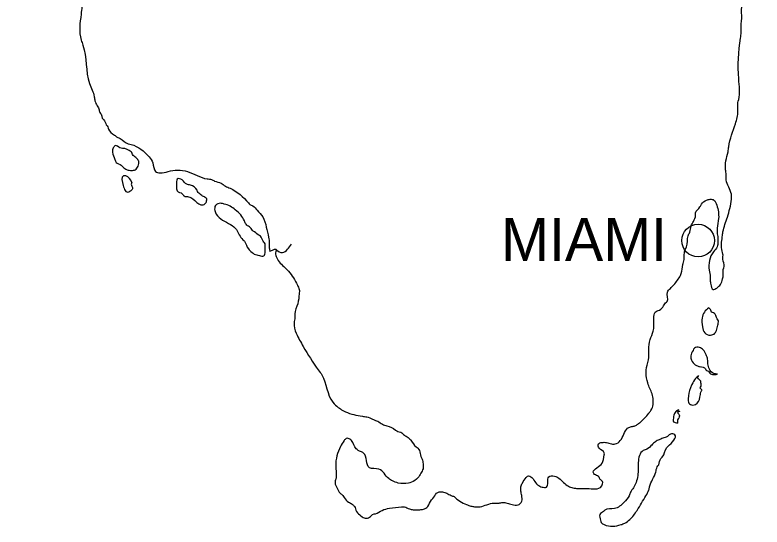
# Model space of a CAD drawing. Extents: x 452225 to 584229, y 1232161 to 1334160.
# Drawn here: x 559573 to 565095, y 1306169 to 1309955 of the extents above; entities that cross this region are included whole.
import ezdxf

# ---------------------------------------------------------------- set-up
doc = ezdxf.new("R2010")
doc.units = 0
doc.layers.add('V-ANNO-SYMB', color=7, linetype='Continuous')

msp = doc.modelspace()

# ---------------------------------------------------------------- linework, layer by layer
at = {"layer": 'V-ANNO-SYMB'}
msp.add_circle((564622, 1308287.4), 120.7, dxfattribs=at)
for points in [[(564684.1, 1308587.1), (564711.1, 1308592.5), (564738.1, 1308587.1), (564759.7, 1308549.3), (564773.2, 1308449.4), (564762.4, 1308379.2), (564762.4, 1308346.8), (564767.8, 1308309), (564767.8, 1308276.6), (564762.4, 1308241.5), (564735.4, 1308203.7), (564703, 1308068.7), (564711.1, 1308017.4), (564711.1, 1307995.8), (564716.5, 1307963.4), (564732.7, 1307925.6), (564759.7, 1307936.4), (564786.7, 1307963.4), (564802.9, 1308003.9), (564808.3, 1308036.3), (564808.3, 1308074.1), (564813.7, 1308095.7), (564805.6, 1308149.7), (564805.6, 1308187.5), (564800.2, 1308209.1), (564800.2, 1308314.4), (564805.6, 1308352.2), (564838, 1308460.2), (564867.7, 1308592.5), (564867.7, 1308630.3), (564829.9, 1308735.6), (564829.9, 1308773.4), (564824.5, 1308811.2), (564827.2, 1308876), (564843.4, 1308943.5), (564848.8, 1308981.3), (564897.4, 1309151.4), (564916.3, 1309243.2), (564916.3, 1309308), (564921.7, 1309329.6), (564921.7, 1309483.5), (564935.2, 1309783.2), (564940.6, 1309826.4), (564940.6, 1309893.9), (564946, 1309937.1), (564943.3, 1310001.9), (564948.7, 1310028.9), (564948.7, 1310072.1), (564954.1, 1310101.8), (564954.1, 1310139.6), (564959.5, 1310166.6), (564959.5, 1310204.4), (564970.3, 1310269.2), (564967.6, 1310307), (564973, 1310347.5), (564973, 1310406.9), (564989.2, 1310487.9), (564989.2, 1310514.9), (565000, 1310560.8), (565000, 1310614.8), (565005.4, 1310652.6), (565002.7, 1310766), (564991.9, 1310838.9), (564991.9, 1310871.3), (564973, 1311000.9), (564973, 1311063), (564967.6, 1311122.4), (564967.6, 1311252), (564973, 1311292.5), (564970.3, 1311395.1), (564975.7, 1311416.7), (564975.7, 1311486.9), (564981.1, 1311527.4), (565002.7, 1311559.8), (565040.5, 1311484.2), (565045.9, 1311449.1), (565056.7, 1311411.3), (565059.4, 1311373.5), (565070.2, 1311308.7), (565070.2, 1311270.9), (565075.6, 1311238.5), (565078.3, 1310998.2), (565072.9, 1310957.7), (565072.9, 1310882.1), (565067.5, 1310849.7), (565067.5, 1310817.3), (565062.1, 1310774.1), (565062.1, 1310752.5), (565078.3, 1310757.9), (565089.1, 1310784.9), (565094.5, 1310828.1)], [(560153.5, 1311370.8), (560180.5, 1311392.4), (560148.1, 1311349.2), (560137.3, 1311338.4), (560029.3, 1311270.9), (559996.9, 1311254.7), (559986.1, 1311233.1), (559964.5, 1311211.5), (559953.7, 1311195.3), (559937.5, 1311184.5), (559932.1, 1311165.6), (559861.9, 1311084.6), (559834.9, 1311063), (559813.3, 1311030.6), (559807.9, 1310995.5), (559797.1, 1310979.3), (559794.4, 1310952.3), (559778.2, 1310914.5), (559756.6, 1310892.9), (559718.8, 1310871.3), (559697.2, 1310855.1), (559659.4, 1310841.6), (559627, 1310836.2), (559594.6, 1310820), (559578.4, 1310776.8), (559573, 1310744.4), (559578.4, 1310712), (559632.4, 1310658), (559654, 1310647.2), (559740.4, 1310620.2), (559807.9, 1310609.4), (559942.9, 1310544.6), (559975.3, 1310517.6), (560013.1, 1310447.4), (560018.5, 1310425.8), (560032, 1310398.8), (560048.2, 1310309.7), (560048.2, 1310277.3), (560053.6, 1310250.3), (560053.6, 1310212.5), (560059, 1310180.1), (560059, 1310126.1), (560067.1, 1310069.4), (560067.1, 1310015.4), (560061.7, 1309961.4), (560061.7, 1309769.7), (560075.2, 1309731.9), (560123.8, 1309448.4), (560158.9, 1309351.2), (560164.3, 1309321.5), (560180.5, 1309283.7), (560191.3, 1309267.5), (560196.7, 1309240.5), (560212.9, 1309213.5), (560218.3, 1309191.9), (560229.1, 1309181.1), (560248, 1309143.3), (560258.8, 1309127.1), (560264.2, 1309110.9), (560307.4, 1309067.7), (560329, 1309051.5), (560350.6, 1309040.7), (560410, 1309002.9), (560431.6, 1308997.5), (560563.9, 1308905.7), (560590.9, 1308862.5), (560612.5, 1308797.7), (560644.9, 1308786.9), (560704.3, 1308797.7), (560847.4, 1308797.7), (560993.2, 1308743.7), (561025.6, 1308738.3), (561047.2, 1308727.5), (561095.8, 1308711.3), (561128.2, 1308689.7), (561163.3, 1308673.5), (561298.3, 1308565.5), (561309.1, 1308554.7), (561330.7, 1308543.9), (561363.1, 1308511.5), (561403.6, 1308462.9), (561430.6, 1308387.3), (561446.8, 1308311.7), (561452.2, 1308268.5), (561452.2, 1308233.4), (561457.6, 1308206.4)], [(560385.7, 1308967.8), (560347.9, 1308973.2), (560315.5, 1308989.4), (560299.3, 1308973.2), (560293.9, 1308940.8), (560310.1, 1308886.8), (560320.9, 1308865.2), (560358.7, 1308843.6), (560369.5, 1308832.8), (560401.9, 1308811.2), (560434.3, 1308805.8), (560461.3, 1308811.2), (560482.9, 1308838.2), (560488.3, 1308876)], [(560488.3, 1308873.3), (560480.2, 1308886.8), (560466.7, 1308900.3), (560453.2, 1308911.1), (560442.4, 1308924.6), (560437, 1308938.1), (560407.3, 1308957), (560385.7, 1308967.8)], [(560437, 1308716.7), (560391.1, 1308765.3), (560374.9, 1308765.3), (560372.2, 1308695.1), (560388.4, 1308657.3), (560399.2, 1308646.5), (560431.6, 1308657.3)], [(560437, 1308716.7), (560431.6, 1308703.2), (560437, 1308689.7), (560442.4, 1308670.8), (560431.6, 1308657.3)], [(560920.3, 1308660), (560869, 1308697.8), (560842, 1308703.2), (560809.6, 1308735.6), (560771.8, 1308741), (560766.4, 1308724.8), (560766.4, 1308687), (560771.8, 1308654.6), (560809.6, 1308633), (560823.1, 1308616.8), (560855.5, 1308611.4), (560887.9, 1308595.2), (560947.3, 1308552), (560963.5, 1308552), (560985.1, 1308568.2), (560990.5, 1308595.2)], [(560990.5, 1308595.2), (560979.7, 1308606), (560966.2, 1308614.1), (560952.7, 1308619.5), (560939.2, 1308633), (560925.7, 1308643.8), (560920.3, 1308660)], [(562818.4, 1306394.7), (562861.6, 1306359.6), (562910.2, 1306335.3), (562942.6, 1306324.5), (562969.6, 1306319.1), (563010.1, 1306319.1), (563112.7, 1306346.1), (563150.5, 1306346.1), (563177.5, 1306351.5), (563209.9, 1306346.1), (563247.7, 1306335.3), (563290.9, 1306332.6), (563317.9, 1306359.6), (563317.9, 1306402.8), (563312.5, 1306435.2), (563312.5, 1306467.6), (563323.3, 1306494.6), (563350.3, 1306535.1), (563361.1, 1306545.9), (563393.5, 1306535.1), (563420.5, 1306497.3), (563452.9, 1306470.3), (563469.1, 1306464.9), (563501.5, 1306464.9), (563517.7, 1306540.5), (563560.9, 1306545.9), (563593.3, 1306529.7), (563663.5, 1306470.3), (563695.9, 1306459.5), (563733.7, 1306454.1), (563801.2, 1306454.1), (563909.2, 1306473), (563914.6, 1306505.4), (563898.4, 1306521.6), (563890.3, 1306537.8), (563863.3, 1306554), (563847.1, 1306575.6), (563874.1, 1306608), (563911.9, 1306640.4), (563928.1, 1306702.5), (563928.1, 1306718.7), (563890.3, 1306751.1), (563884.9, 1306783.5), (563911.9, 1306794.3), (563944.3, 1306794.3), (563982.1, 1306783.5), (564009.1, 1306783.5), (564046.9, 1306807.8), (564100.9, 1306899.6), (564122.5, 1306910.4), (564149.5, 1306915.8), (564171.1, 1306926.6), (564192.7, 1306942.8), (564257.5, 1307010.3), (564273.7, 1307031.9), (564289.9, 1307075.1), (564289.9, 1307107.5), (564287.2, 1307131.8), (564281.8, 1307153.4), (564249.4, 1307234.4), (564249.4, 1307385.6), (564254.8, 1307404.5), (564257.5, 1307480.1), (564268.3, 1307555.7), (564289.9, 1307617.8), (564295.3, 1307655.6), (564295.3, 1307725.8), (564311.5, 1307763.6), (564327.7, 1307769), (564360.1, 1307796), (564381.7, 1307825.7), (564392.5, 1307836.5), (564395.2, 1307906.7), (564416.8, 1307933.7), (564427.6, 1307944.5), (564481.6, 1308012), (564497.8, 1308044.4), (564508.6, 1308109.2), (564519.4, 1308147), (564519.4, 1308174), (564524.8, 1308214.5), (564535.6, 1308241.5), (564549.1, 1308322.5), (564559.9, 1308349.5), (564570.7, 1308395.4), (564586.9, 1308427.8), (564603.1, 1308476.4), (564603.1, 1308492.6), (564635.5, 1308535.8), (564646.3, 1308557.4), (564684.1, 1308587.1)], [(561268.6, 1308433.2), (561241.6, 1308476.4), (561201.1, 1308514.2), (561163.3, 1308541.2), (561120.1, 1308557.4), (561093.1, 1308562.8), (561055.3, 1308546.6), (561049.9, 1308508.8), (561060.7, 1308481.8), (561106.6, 1308438.6), (561166, 1308406.2), (561209.2, 1308368.4), (561230.8, 1308330.6), (561257.8, 1308292.8), (561268.6, 1308282), (561298.3, 1308225.3), (561309.1, 1308214.5), (561341.5, 1308187.5), (561379.3, 1308176.7), (561411.7, 1308174), (561422.5, 1308206.4), (561422.5, 1308233.4), (561417.1, 1308271.2), (561406.3, 1308282), (561398.2, 1308303.6), (561371.2, 1308330.6), (561333.4, 1308357.6)], [(561333.4, 1308357.6), (561322.6, 1308368.4), (561314.5, 1308381.9), (561298.3, 1308392.7), (561276.7, 1308414.3), (561265.9, 1308435.9)], [(561503.5, 1308219.9), (561549.4, 1308198.3), (561587.2, 1308222.6), (561616.9, 1308260.4)], [(561457.6, 1308209.1), (561506.2, 1308219.9), (561500.8, 1308206.4), (561503.5, 1308168.6), (561525.1, 1308130.8), (561595.3, 1308060.6), (561660.1, 1307958), (561673.6, 1307925.6), (561673.6, 1307893.2), (561662.8, 1307820.3), (561641.2, 1307744.7), (561641.2, 1307717.7), (561635.8, 1307679.9), (561652, 1307601.6), (561703.3, 1307504.4), (561814, 1307331.6), (561841, 1307293.8), (561922, 1307091.3), (561962.5, 1307053.5), (561994.9, 1307031.9), (562016.5, 1307021.1), (562140.7, 1306988.7), (562173.1, 1306983.3), (562216.3, 1306967.1), (562237.9, 1306956.3), (562254.1, 1306950.9), (562289.2, 1306929.3), (562321.6, 1306918.5), (562386.4, 1306886.1), (562402.6, 1306875.3), (562424.2, 1306869.9), (562451.2, 1306848.3), (562478.2, 1306832.1), (562499.8, 1306810.5), (562537.6, 1306761.9), (562551.1, 1306751.1), (562561.9, 1306734.9), (562572.7, 1306691.7), (562583.5, 1306670.1), (562588.9, 1306637.7), (562588.9, 1306599.9), (562572.7, 1306567.5), (562551.1, 1306532.4), (562502.5, 1306500), (562480.9, 1306494.6), (562405.3, 1306494.6), (562362.1, 1306510.8), (562335.1, 1306527), (562262.2, 1306597.2), (562192, 1306608), (562148.8, 1306716), (562127.2, 1306726.8), (562094.8, 1306748.4), (562059.7, 1306807.8), (562048.9, 1306818.6), (562021.9, 1306824), (562005.7, 1306807.8), (561978.7, 1306764.6), (561943.6, 1306621.5), (561943.6, 1306524.3), (561938.2, 1306497.3), (561954.4, 1306456.8), (561976, 1306419), (561994.9, 1306402.8), (562005.7, 1306386.6), (562038.1, 1306354.2), (562065.1, 1306338), (562081.3, 1306321.8), (562097.5, 1306284), (562129.9, 1306251.6), (562146.1, 1306240.8), (562178.5, 1306235.4), (562205.5, 1306251.6), (562216.3, 1306262.4), (562237.9, 1306267.8), (562286.5, 1306292.1), (562340.5, 1306308.3), (562429.6, 1306319.1), (562451.2, 1306319.1), (562489, 1306302.9), (562516, 1306297.5), (562564.6, 1306297.5), (562591.6, 1306300.2), (562624, 1306321.8), (562651, 1306370.4), (562661.8, 1306381.2), (562688.8, 1306419), (562732, 1306429.8), (562764.4, 1306419), (562796.8, 1306402.8), (562818.4, 1306394.7)], [(564700.3, 1307790.6), (564667.9, 1307758.2), (564651.7, 1307715), (564654.4, 1307650.2), (564670.6, 1307604.3), (564713.8, 1307588.1), (564746.2, 1307601.6), (564757, 1307623.2), (564767.8, 1307661), (564773.2, 1307693.4)], [(564773.2, 1307693.4), (564762.4, 1307709.6), (564748.9, 1307742), (564735.4, 1307752.8), (564721.9, 1307758.2), (564716.5, 1307771.7), (564697.6, 1307790.6)], [(564765.1, 1307299.2), (564738.1, 1307304.6), (564705.7, 1307337), (564694.9, 1307374.8), (564692.2, 1307409.9), (564681.4, 1307442.3), (564659.8, 1307480.1), (564632.8, 1307496.3), (564595, 1307490.9), (564584.2, 1307474.7), (564568, 1307434.2), (564573.4, 1307401.8), (564600.4, 1307369.4), (564638.2, 1307353.2)], [(564635.5, 1307355.9), (564676, 1307339.7), (564684.1, 1307326.2), (564697.6, 1307320.8), (564708.4, 1307307.3), (564735.4, 1307296.5), (564762.4, 1307299.2)], [(564624.7, 1307288.4), (564603.1, 1307266.8), (564576.1, 1307223.6), (564565.3, 1307199.3), (564549.1, 1307118.3), (564554.5, 1307085.9), (564565.3, 1307075.1), (564603.1, 1307075.1), (564635.5, 1307129.1), (564640.9, 1307166.9)], [(564640.9, 1307166.9), (564649, 1307183.1), (564638.2, 1307196.6), (564643.6, 1307210.1), (564643.6, 1307229), (564638.2, 1307253.3), (564624.7, 1307264.1), (564616.6, 1307283)], [(564478.9, 1307034.6), (564457.3, 1307023.8), (564441.1, 1306986), (564441.1, 1306948.2), (564470.8, 1306937.4)], [(564465.4, 1307029.2), (564484.3, 1307023.8), (564470.8, 1307018.4), (564478.9, 1307004.9), (564484.3, 1306991.4), (564478.9, 1306975.2), (564470.8, 1306961.7), (564470.8, 1306937.4)], [(564281.8, 1306778.1), (564244, 1306745.7), (564217, 1306734.9), (564179.2, 1306645.8), (564179.2, 1306602.6), (564163, 1306497.3), (564144.1, 1306459.5), (564122.5, 1306427.1), (564111.7, 1306400.1), (564073.9, 1306351.5), (564003.7, 1306305.6), (563933.5, 1306294.8), (563922.7, 1306284), (563895.7, 1306262.4), (563901.1, 1306219.2), (563906.5, 1306203), (563928.1, 1306186.8), (564052.3, 1306186.8), (564079.3, 1306197.6), (564117.1, 1306224.6), (564171.1, 1306292.1), (564235.9, 1306400.1), (564257.5, 1306443.3), (564262.9, 1306467.6), (564308.8, 1306575.6), (564319.6, 1306613.4), (564330.4, 1306629.6), (564346.6, 1306675.5), (564357.4, 1306686.3), (564389.8, 1306756.5), (564400.6, 1306767.3), (564449.2, 1306851), (564416.8, 1306856.4), (564400.6, 1306842.9)], [(564400.6, 1306842.9), (564379, 1306832.1), (564360.1, 1306826.7), (564346.6, 1306818.6), (564319.6, 1306807.8), (564306.1, 1306799.7), (564279.1, 1306775.4)]]:
    msp.add_spline(points, degree=3, dxfattribs=at)

# ---------------------------------------------------------------- texts
msp.add_text('MIAMI', height=317.52, rotation=0, dxfattribs=at).set_placement((563165.7, 1308135.9))

doc.saveas('drawing.dxf')
